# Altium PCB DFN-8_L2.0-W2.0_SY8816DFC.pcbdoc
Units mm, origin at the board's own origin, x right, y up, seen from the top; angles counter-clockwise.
Board outline 15.4 x 15.9 mm, 2 copper layers (Top Layer, Bottom Layer), stack 0 mm thick; 1 components, 0 nets, 8 pads, 0 vias.
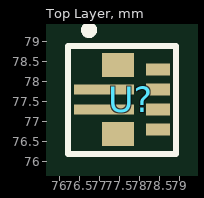
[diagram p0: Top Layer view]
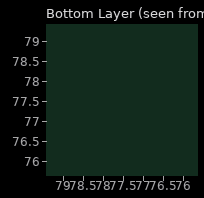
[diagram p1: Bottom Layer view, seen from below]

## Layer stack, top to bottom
Top Layer: signal copper (thickness not stored)
Bottom Layer: signal copper (thickness not stored)

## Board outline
85.25,69.85 69.85,69.85 69.85,85.747 85.25,85.747

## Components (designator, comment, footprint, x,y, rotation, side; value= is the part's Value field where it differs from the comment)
U? "" DFN-8_L2.0-W2.0_SY8816DFC 77.774,77.561 r0 top

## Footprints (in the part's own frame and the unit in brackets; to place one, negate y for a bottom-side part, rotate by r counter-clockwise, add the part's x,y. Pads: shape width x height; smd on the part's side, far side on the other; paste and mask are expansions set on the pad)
DFN-8_L2.0-W2.0_SY8816DFC [mm]
  rect 0.8x0.595 smd: 1(-0.325,0.865) 4(-0.325,-0.865)
  rect 1.5x0.25 smd: 2(-0.675,0.25) 3(-0.675,-0.25)
  rect 0.6x0.3 smd: 5(0.675,-0.75) 6(0.675,-0.25) 7(0.675,0.25) 8(0.675,0.75)
  silkscreen extent -1.57,-1.36 1.13,1.84

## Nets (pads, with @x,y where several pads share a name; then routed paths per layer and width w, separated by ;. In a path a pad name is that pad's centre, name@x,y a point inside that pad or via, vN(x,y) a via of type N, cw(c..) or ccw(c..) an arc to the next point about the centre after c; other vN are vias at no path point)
pads on no net: U?.1 U?.2 U?.3 U?.4 U?.5 U?.6 U?.7 U?.8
